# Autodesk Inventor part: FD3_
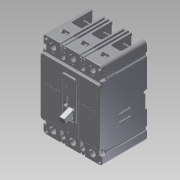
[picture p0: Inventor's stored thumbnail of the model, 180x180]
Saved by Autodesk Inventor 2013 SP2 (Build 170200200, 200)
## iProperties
Created: 2014-08
Part Number: FD3_
Material: Generic
Document SubType Name: Modeling
Designer: DM/JS
Density: 1 g/cm^3
Description: TYPE FD THERMAL MAGNETIC CIRCUIT BREAKERS THREE POLE, SERIES C
Translation Standard: STEP AP214IS
FileName: Y:\ECO-062745\WIP\New\FD3_.stp
PreProcessor: Autodesk Inventor 2012
PostProcessor: Build: 219, Release: 2012 SP2 - Date: Fri 04/27/2012
Sent Units: inch
Uncertainty: 0.00039370078740199997
MXEDIT: false
MXINVTNRV: INV Versioned Component|FD3_|003.0
Author: DM/JS
Revision Number: 003
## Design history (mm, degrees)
node "FD3_"
node "L1"
node "L2"
node "L3"
node "T1"
node "T2"
node "T3"
body "Solid1"
node "Base1"
